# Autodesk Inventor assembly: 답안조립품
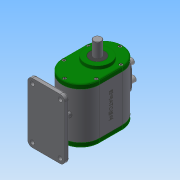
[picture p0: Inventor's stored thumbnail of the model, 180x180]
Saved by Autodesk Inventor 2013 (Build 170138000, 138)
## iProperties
Created: 2018-10
Part Number: 답안조립품
Document SubType Name: Assembly
Designer: Administrator
Author: Administrator
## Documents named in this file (15)
- C:\Users\Administrator\Desktop\381007V1032\답안조립품.iam
- C:\Users\Administrator\Desktop\381007V1032\본체.ipt
- C:\Users\Administrator\Desktop\381007V1032\가변스프링1.ipt
- C:\Users\Administrator\Desktop\381007V1032\가변스프링2.ipt
- C:\Users\Administrator\Desktop\381007V1032\뒤커버.ipt
- C:\Users\Administrator\Desktop\381007V1032\메인축.ipt
- C:\Users\Administrator\Desktop\381007V1032\베어링 608.ipt
- C:\Users\Administrator\Desktop\381007V1032\베어링 6003.ipt
- C:\Users\Administrator\Desktop\381007V1032\볼트 M4.ipt
- C:\Users\Administrator\Desktop\381007V1032\부시.ipt
- C:\Users\Administrator\Desktop\381007V1032\서브축.ipt
- C:\Users\Administrator\Desktop\381007V1032\슬라이더.ipt
- C:\Users\Administrator\Desktop\381007V1032\앞커버.ipt
- C:\Users\Administrator\Desktop\381007V1032\오일실 8 22 7.ipt
- C:\Users\Administrator\Desktop\381007V1032\오일실 17 32 8.ipt
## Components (2 placed, 2 different names)
1. 가변스프링1:1
2. 가변스프링2:1
